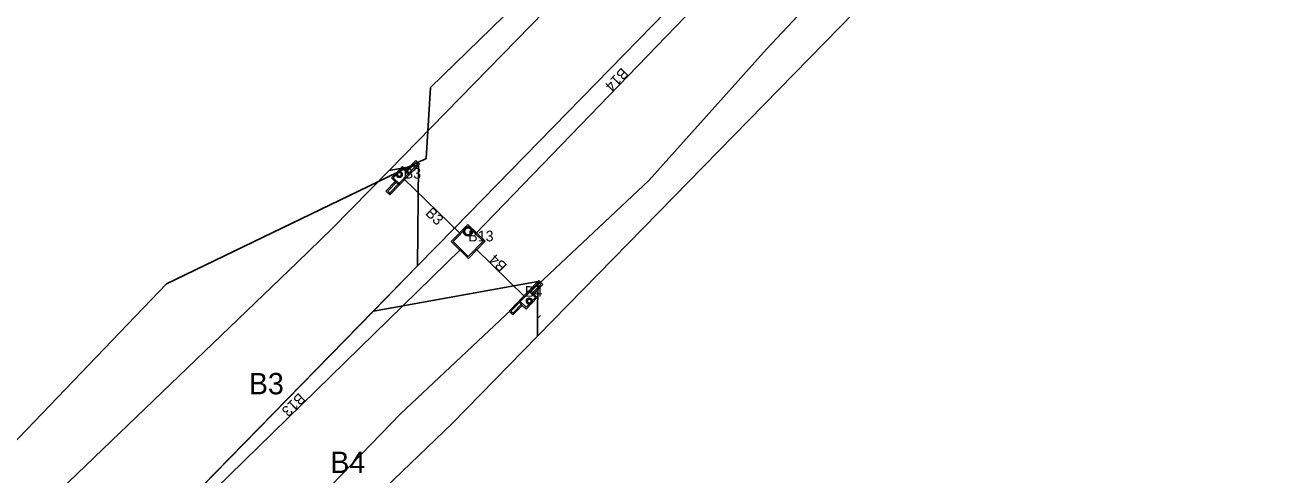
# Model space of a CAD drawing. Extents: x 2253035 to 2279930, y 13774972 to 13793443.
# Drawn here: x 2255239.2 to 2255713, y 13791184.9 to 13791353.4 of the extents above; entities that cross this region are included whole.
import ezdxf

# ---------------------------------------------------------------- set-up
doc = ezdxf.new("R2010")
doc.units = 0
for name, color, linetype in [('E_Utility_ATT_Fiber', 7, 'Continuous'), ('E_Utility_ATT_Xbox', 7, 'Continuous'), ('E_Utility_Fiber Optic_Fiber Optic Cable_FOC', 7, 'Continuous'), ('E_Utility_Gas_Gas Line_GL_Description', 7, 'Continuous'), ('E_Utility_Gas_Gas Line_GL_Elevation', 7, 'Continuous'), ('E_Utility_Water_Water Valve_WV_Elevation', 7, 'Continuous')]:
    doc.layers.add(name, color=color, linetype=linetype)

msp = doc.modelspace()

# ---------------------------------------------------------------- linework, layer by layer
at = {"layer": 'E_Utility_ATT_Fiber'}
for p, q in [((2255431.07, 13791236.79), (2255713.03, 13791525.45)), ((2255475.74, 13791401.64), (2255375.55, 13791298.97)), ((2255400.01, 13791277.4), (2255520.76, 13791401.16)), ((2255520.77, 13791401.15), (2255400.01, 13791277.4)), ((2255386.59, 13791300.94), (2255375.55, 13791298.97)), ((2255375.55, 13791298.97), (2255386.59, 13791300.94)), ((2255386.15, 13791263.21), (2255386.59, 13791300.94)), ((2255386.59, 13791300.94), (2255386.15, 13791263.21)), ((2255386.15, 13791263.21), (2255400.01, 13791277.4)), ((2255431.31, 13791257.32), (2255369.63, 13791246.27)), ((2255369.63, 13791246.27), (2255431.31, 13791257.32)), ((2255431.15, 13791243.45), (2255431.31, 13791257.32)), ((2255431.31, 13791257.32), (2255431.15, 13791243.45)), ((2255369.63, 13791246.27), (2255331.7, 13791207.4)), ((2255431.07, 13791236.79), (2255431.15, 13791243.45)), ((2255431.15, 13791243.45), (2255431.07, 13791236.79)), ((2255431.15, 13791243.45), (2255432.28, 13791244.61)), ((2255432.28, 13791244.61), (2255431.15, 13791243.45)), ((2255399.18, 13791204.14), (2255431.07, 13791236.79)), ((2255331.7, 13791207.4), (2255289.47, 13791164.26)), ((2255307.2, 13791115.81), (2255399.18, 13791204.14))]:
    msp.add_line(p, q, dxfattribs=at)
for points in [[(2255375.55, 13791298.97), (2255354.02, 13791277.09), (2255341.17, 13791264.54), (2255249.13, 13791176.15)], [(2255400.01, 13791277.4), (2255386.15, 13791263.2), (2255369.63, 13791246.27)], [(2255289.47, 13791164.26), (2255369.58, 13791246.26), (2255386.15, 13791263.21)]]:
    msp.add_lwpolyline(points, dxfattribs=at)
at = {"layer": 'E_Utility_ATT_Xbox'}
for p, q in [((2255378.83, 13791298.03), (2255378.83, 13791298.03)), ((2255381.65, 13791298.78), (2255381.65, 13791298.78)), ((2255378.16, 13791295.2), (2255378.16, 13791295.2)), ((2255379.9, 13791296.99), (2255379.9, 13791296.99)), ((2255380.97, 13791295.94), (2255380.97, 13791295.94)), ((2255402.28, 13791275.17), (2255402.28, 13791275.17)), ((2255407.93, 13791275.24), (2255407.93, 13791275.24)), ((2255402.34, 13791269.51), (2255402.34, 13791269.51)), ((2255405.14, 13791272.38), (2255405.14, 13791272.38)), ((2255408, 13791269.58), (2255408, 13791269.58)), ((2255426.43, 13791251.6), (2255426.43, 13791251.6)), ((2255427.5, 13791250.55), (2255427.5, 13791250.55)), ((2255429.25, 13791252.34), (2255429.25, 13791252.34)), ((2255425.76, 13791248.76), (2255425.76, 13791248.76)), ((2255428.58, 13791249.5), (2255428.58, 13791249.5))]:
    msp.add_line(p, q, dxfattribs=at)
at = {"layer": 'E_Utility_Fiber Optic_Fiber Optic Cable_FOC'}
for p, q in [((2255382, 13791299.13), (2255385.49, 13791302.71)), ((2255385.49, 13791302.71), (2255386.92, 13791301.31)), ((2255375.74, 13791290.57), (2255386.21, 13791301.31)), ((2255375.75, 13791289.86), (2255386.92, 13791301.31)), ((2255376.37, 13791296.24), (2255380.57, 13791300.53)), ((2255377.08, 13791296.24), (2255380.57, 13791299.82)), ((2255380.57, 13791300.53), (2255382, 13791299.13)), ((2255380.57, 13791299.82), (2255383.08, 13791297.38)), ((2255382, 13791299.13), (2255383.43, 13791297.74)), ((2255382.01, 13791298.43), (2255385.5, 13791302)), ((2255385.5, 13791302), (2255386.57, 13791300.96)), ((2255374.31, 13791291.26), (2255377.81, 13791294.84)), ((2255375.02, 13791291.27), (2255378.51, 13791294.85)), ((2255376.37, 13791296.24), (2255377.81, 13791294.84)), ((2255377.08, 13791296.24), (2255379.59, 13791293.8)), ((2255377.81, 13791294.84), (2255379.24, 13791293.44)), ((2255374.31, 13791291.26), (2255375.75, 13791289.86)), ((2255375.02, 13791291.27), (2255376.09, 13791290.22)), ((2255398.77, 13791272.3), (2255405.06, 13791278.74)), ((2255405.06, 13791278.74), (2255411.5, 13791272.45)), ((2255399.48, 13791272.31), (2255405.07, 13791278.03)), ((2255405.07, 13791278.03), (2255410.79, 13791272.44)), ((2255405.22, 13791266.01), (2255398.77, 13791272.3)), ((2255405.21, 13791266.72), (2255399.48, 13791272.31)), ((2255410.79, 13791272.44), (2255405.21, 13791266.72)), ((2255411.5, 13791272.45), (2255405.22, 13791266.01)), ((2255431.66, 13791257.67), (2255420.49, 13791246.22)), ((2255431.67, 13791256.97), (2255421.19, 13791246.23)), ((2255432.38, 13791256.27), (2255428.89, 13791252.69)), ((2255433.09, 13791256.28), (2255429.6, 13791252.7)), ((2255432.38, 13791256.27), (2255431.31, 13791257.32)), ((2255433.09, 13791256.28), (2255431.66, 13791257.67)), ((2255430.32, 13791251.29), (2255426.83, 13791247.71)), ((2255431.03, 13791251.3), (2255426.84, 13791247.01)), ((2255430.32, 13791251.29), (2255427.82, 13791253.74)), ((2255429.6, 13791252.7), (2255428.17, 13791254.09)), ((2255431.03, 13791251.3), (2255429.6, 13791252.7)), ((2255421.92, 13791244.83), (2255420.49, 13791246.22)), ((2255421.91, 13791245.53), (2255420.83, 13791246.58)), ((2255425.4, 13791249.11), (2255421.91, 13791245.53)), ((2255425.41, 13791248.4), (2255421.92, 13791244.83)), ((2255425.41, 13791248.4), (2255423.98, 13791249.8)), ((2255426.83, 13791247.71), (2255424.33, 13791250.16)), ((2255426.84, 13791247.01), (2255425.41, 13791248.4))]:
    msp.add_line(p, q, dxfattribs=at)
for centre, radius in [((2255379.36, 13791297.51), 1.08), ((2255379.36, 13791297.51), 0.75), ((2255405.09, 13791276.15), 1.67), ((2255405.09, 13791276.15), 1.33), ((2255428.04, 13791250.03), 1.08), ((2255428.04, 13791250.03), 0.75)]:
    msp.add_circle(centre, radius, dxfattribs=at)
at = {"layer": 'E_Utility_Gas_Gas Line_GL_Description'}
for p, q in [((2255523.2, 13791394.79), (2255407.93, 13791275.24)), ((2255380.97, 13791295.94), (2255402.28, 13791275.17)), ((2255402.34, 13791269.51), (2255286.71, 13791156.44)), ((2255426.43, 13791251.6), (2255408, 13791269.58))]:
    msp.add_line(p, q, dxfattribs=at)
at = {"layer": 'E_Utility_Water_Water Valve_WV_Elevation'}
msp.add_lwpolyline([(2255623, 13791457.45), (2255517, 13791344.43), (2255472.8, 13791295.19), (2255379.75, 13791207.78), (2255198.17, 13791020.02), (2255136.03, 13790956.76), (2255067.98, 13791022.64), (2255178.24, 13791137.81), (2255292.07, 13791256.47), (2255389.41, 13791303.46), (2255390.98, 13791330.06), (2255459.85, 13791397.22)], dxfattribs=at)

# ---------------------------------------------------------------- texts
at = {"layer": 'E_Utility_Gas_Gas Line_GL_Elevation'}
for s, rotation, p in [('B14', 226.0454, (2255462.69, 13791337.79)), ('B3', 315.7227, (2255388.83, 13791282.69)), ('B4', 135.7035, (2255420.01, 13791263.45)), ('B13', 224.3592, (2255341.73, 13791215.83))]:
    msp.add_text(s, height=4, rotation=rotation, dxfattribs=at).set_placement(p)
for s, height, p in [('B3', 4, (2255380.97, 13791295.94)), ('B13', 4, (2255405.14, 13791272.38)), ('B4', 4, (2255426.43, 13791251.6)), ('B3', 8, (2255322.98, 13791215.05)), ('B4', 8, (2255353.5, 13791185.54))]:
    msp.add_text(s, height=height, dxfattribs=at).set_placement(p)

doc.saveas('drawing.dxf')
